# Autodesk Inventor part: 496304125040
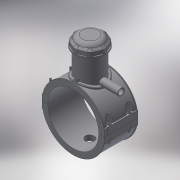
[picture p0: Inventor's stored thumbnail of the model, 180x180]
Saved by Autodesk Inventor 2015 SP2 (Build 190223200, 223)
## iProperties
Created: 2017-07
Part Number: 496304125040
Material: Generic
Description: PLASSON TAPPING SADDLE 125x40
Document SubType Name: Modeling
Designer: KIM
Mass: 844.49 g
Surface Area: 1915.11 cm^2
Volume: 844.49 cm^3
Density: 1 g/cm^3
Appearance: Default
Author: KIM
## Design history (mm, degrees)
derived "496304.ipt"
feature "Solid1::496304.ipt"
feature "Solid2::496304.ipt"
feature "Solid4::496304.ipt"
feature "Solid5::496304.ipt"
tag "TaggingFeature1"
body "Solid1"
body "Solid2"
other parameters: "d0" = 125, "d2" = 162, "d3" = 31.25, "d4" = 118, "d5" = 0, "d6" = 0.1, "d8" = 0, "d19" = 6, "d20" = 6, "d21" = 70.8, "d23" = 0, "d24" = 35.4, "d26" = 0, "d29" = 3, "d30" = 41.66667, "d31" = 6, "d32" = 0, "d33" = 0, "d34" = 0.6, "d40" = 78, "d41" = 62.5, "d43" = 0, "d45" = 0, "d47" = 145.8, "d70" = 15, "d72" = 0, "d73" = 6, "d75" = 5, "d76" = 0, "d77" = 6.25, "d78" = 92.5, "d79" = 15, "d80" = 47.2, "d82" = 5 deg, "d84" = 4, "d85" = 14, "d86" = 0, "d87" = 3, "d88" = 0, "d89" = 1, "d90" = 1, "d91" = 94.4, "d92" = 0, "d93" = 0.5, "d94" = 65.78947, "d96" = 153, "d97" = 2.36, "d98" = 0, "d102" = 1.25, "d120" = 140 deg, "d121" = 24.228, "d122" = 20 deg, "d126" = 0, "d143" = 128.75, "d145" = 19.23077, "d149" = 1.875, "d150" = 21.15385, "d153" = 118, "d154" = 0, "d156" = 75, "d157" = 160 deg, "d159" = 5, "d161" = 1.875, "d162" = 70.8, "d163" = 0, "d164" = 62.5, "d167" = 12.5, "d168" = 73.17073, "d170" = 3.375, "d172" = 0, "d173" = 1, "d175" = 62.5, "d176" = 20 deg, "d177" = 8.75, "d178" = 25, "d180" = 0, "d184" = 7, "d185" = 38.35, "d186" = 38.35, "d187" = 75, "d188" = 7.5, "d189" = 8.75, "d190" = 0, "d191" = 112.5, "d193" = 6.3, "d194" = 4.13, "d195" = 90 deg, "d197" = 0, "d199" = 0, "d200" = 12.5, "d202" = 0, "d203" = 114, "d204" = 59.375, "d205" = 43.75, "d206" = 53.125, "d207" = 85.5, "d208" = 88.92, "d209" = 106.02, "d210" = 53.75, "d211" = 62.5, "d213" = 0.9, "d216" = 0, "d217" = 12.5, "d218" = 12.5, "d219" = 2.5, "d222" = 125, "d224" = 0, "d230" = 5, "d233" = 6, "d236" = 81, "d237" = 35.4, "d238" = 6.02433, "d240" = 35.4, "d241" = 35.4, "d242" = 35.4, "d243" = 6, "d244" = 35.4, "d245" = 35.4, "d246" = 35.4, "d247" = 6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
